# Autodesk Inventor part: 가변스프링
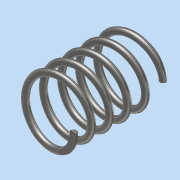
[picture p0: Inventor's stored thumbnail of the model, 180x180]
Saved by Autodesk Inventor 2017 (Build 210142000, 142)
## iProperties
Part Number: 가변스프링
Material: 스테인레스 스틸
Document SubType Name: Modeling
Designer: MRC
Density: 8 g/cm^3
Appearance: 반연마
Mass: 6.99701 g
Surface Area: 17.7559 cm^2
Volume: 0.874626 cm^3
Author: MRC
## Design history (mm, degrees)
sketch "스케치1"
  geometry: L1 (0, 0)-(9, 0); L2 (9, 28.5)-(0, 28.5); L3 (0, 28.5)-(0, 0); C1 r 1 at (9, 0)
  constraints: 6 end point, 2 parallel, 1 centre point, 1 coincident, 1 horizontal, 1 vertical
  dimensions: "d0" = 9 distance of L1.start L1.end; "d1" = 28.5 distance of L2.end L1.start (derived); "d2" = 2 diameter of C1
feature "코일1" sketch "스케치1" pitch "d3" = 10; turns "d5" = 5; dims "d4" = 28.5 (= d1), "d6" = 0, angle "d7" = 90 deg, angle "d8" = 90 deg, "d9" = 0, "d10" = 0
sketch "스케치2"
  geometry: L1 (28.5, 20)-(0, 20); L2 (0, 20)-(0, -20); L3 (0, -20)-(28.5, -20); L4 (28.5, -20)-(28.5, 20); 2 further points
  constraints: 8 end point, 2 parallel, 1 coincident, 1 horizontal, 1 midpoint, 1 perpendicular
  dimensions: "d11" = 28.5 distance of L2.end L3.end (= d1); "d14" = 40 distance of L3.end L1.start
extrude "돌출1" sketch "스케치2" stored distance "d12" = 0; taper "d13" = 0 deg
node "솔리드1"
